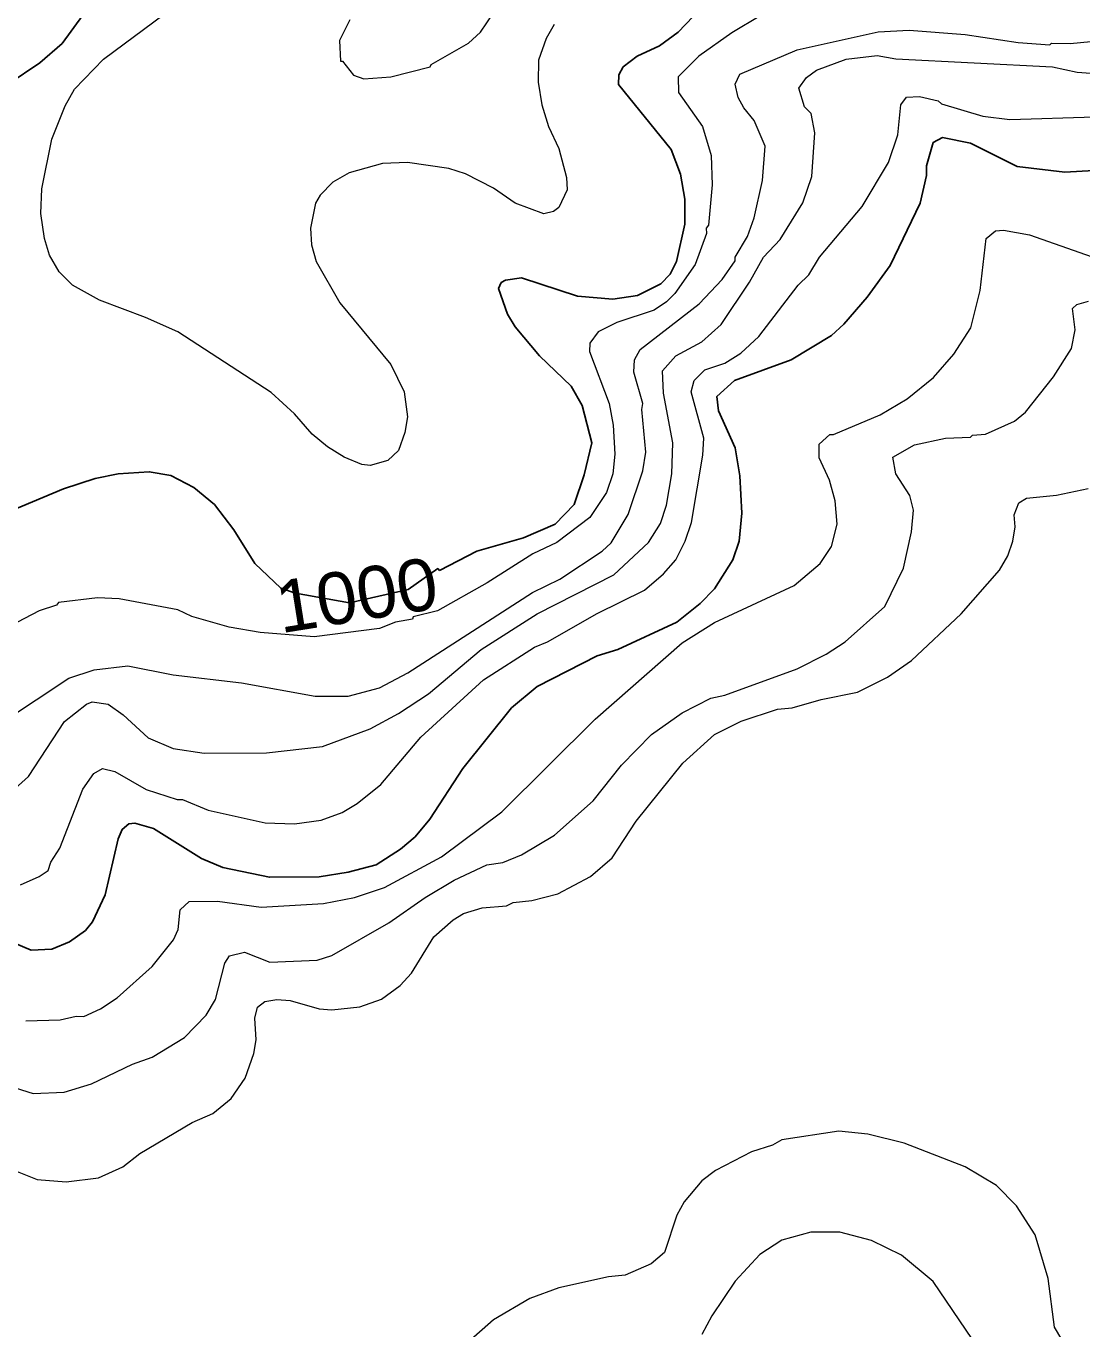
# Model space of a CAD drawing. Extents: x 265.7 to 292.1, y 7676.2 to 7704.2.
# Drawn here: x 286.697 to 288.322, y 7686.96 to 7688.966 of the extents above; entities that cross this region are included whole.
import ezdxf
from ezdxf.enums import TextEntityAlignment as Align

# ---------------------------------------------------------------- set-up
doc = ezdxf.new("R2010")
doc.units = 0
doc.header["$LTSCALE"] = 0.032
doc.layers.add('1', color=7, linetype='Continuous', lineweight=25)
doc.layers.add('2', color=7, linetype='Continuous', lineweight=13)
doc.layers.add('61', color=7, linetype='Continuous')

msp = doc.modelspace()

# ---------------------------------------------------------------- linework, layer by layer
at = {"layer": '1'}
for points in [[(286.6055, 7689.6411), (286.7013, 7689.6012), (286.7651, 7689.5605), (286.8672, 7689.4847), (286.9646, 7689.4001), (287.0276, 7689.3371), (287.1002, 7689.278), (287.1034, 7689.2541), (287.0875, 7689.2293), (287.0308, 7689.1886), (287.0061, 7689.1751), (286.9997, 7689.1751), (286.9933, 7689.1679), (286.955, 7689.1471), (286.8688, 7689.0841), (286.8297, 7689.0458), (286.7523, 7688.9389), (286.718, 7688.9094), (286.6199, 7688.8439)], [(286.659, 7688.2135), (286.7547, 7688.2534), (286.8034, 7688.2694), (286.8385, 7688.2766), (286.8864, 7688.2798), (286.9199, 7688.2742), (286.955, 7688.2558), (286.9869, 7688.2295), (287.0165, 7688.1904), (287.0492, 7688.1385), (287.0892, 7688.1006), (287.1118, 7688.093), (287.1947, 7688.0779), (287.2852, 7688.0987), (287.3304, 7688.1308), (287.3333, 7688.1281), (287.3907, 7688.1577), (287.4625, 7688.1784), (287.5112, 7688.1992), (287.5407, 7688.2295), (287.5559, 7688.275), (287.5678, 7688.3245), (287.5527, 7688.3819), (287.5359, 7688.4114), (287.4872, 7688.4585), (287.4497, 7688.5032), (287.4378, 7688.5223), (287.4242, 7688.5622), (287.4282, 7688.571), (287.4346, 7688.575), (287.4593, 7688.5782), (287.5455, 7688.5503), (287.5998, 7688.5455), (287.6381, 7688.5511), (287.674, 7688.5694), (287.6883, 7688.5838), (287.6979, 7688.6037), (287.7107, 7688.6612), (287.7107, 7688.6995), (287.7043, 7688.7378), (287.6899, 7688.7761), (287.6085, 7688.8758), (287.6093, 7688.891), (287.6157, 7688.903), (287.6373, 7688.9197), (287.6716, 7688.9357), (287.7003, 7688.9564), (287.7578, 7689.0171)], [(286.7045, 7687.5432), (286.7364, 7687.5448), (286.7635, 7687.556), (286.7882, 7687.5736), (286.7994, 7687.5871), (286.8186, 7687.6286), (286.8385, 7687.7148), (286.8449, 7687.7292), (286.8553, 7687.7379), (286.8641, 7687.7387), (286.8928, 7687.7308), (286.967, 7687.6845), (286.9997, 7687.6709), (287.0715, 7687.6557), (287.1481, 7687.6565), (287.1928, 7687.6637), (287.2359, 7687.6749), (287.2734, 7687.6988), (287.2957, 7687.718), (287.3181, 7687.7451), (287.3692, 7687.8233), (287.4442, 7687.9167), (287.4833, 7687.9494), (287.5758, 7687.9965), (287.6078, 7688.0061), (287.6987, 7688.0483), (287.7346, 7688.0771), (287.7562, 7688.0994), (287.7849, 7688.1441), (287.7945, 7688.1728), (287.7985, 7688.2159), (287.7953, 7688.2734), (287.7881, 7688.3165), (287.7626, 7688.3739), (287.7602, 7688.3955), (287.7873, 7688.4202), (287.8743, 7688.4521), (287.9365, 7688.4896), (287.9557, 7688.5072), (287.9916, 7688.5487), (288.0267, 7688.5973), (288.073, 7688.6931), (288.0825, 7688.7362), (288.0825, 7688.7506), (288.0929, 7688.7865), (288.1073, 7688.7944), (288.1504, 7688.7857), (288.2222, 7688.7498), (288.2956, 7688.741), (288.3403, 7688.7434)], [(286.5193, 7687.5313), (286.5249, 7687.56), (286.5385, 7687.5887), (286.5465, 7687.5967), (286.5624, 7687.5999), (286.5768, 7687.5975), (286.7045, 7687.5432)]]:
    msp.add_lwpolyline(points, dxfattribs=at)
at = {"layer": '2'}
for points in [[(287.1952, 7688.9756), (287.1792, 7688.9437), (287.1808, 7688.9118), (287.184, 7688.9118), (287.2008, 7688.8902), (287.2168, 7688.8846), (287.2583, 7688.8878), (287.3189, 7688.903), (287.3205, 7688.907), (287.3779, 7688.9397), (287.3963, 7688.9564), (287.4258, 7688.9995)], [(287.828, 7688.982), (287.7833, 7688.9556), (287.7322, 7688.9197), (287.7003, 7688.8878), (287.7011, 7688.8639), (287.7378, 7688.8112), (287.7514, 7688.7665), (287.753, 7688.7218), (287.7474, 7688.6596), (287.7434, 7688.6548), (287.7442, 7688.6468), (287.7266, 7688.599), (287.6955, 7688.5543), (287.6828, 7688.5415), (287.6636, 7688.5287), (287.6062, 7688.5096), (287.5774, 7688.4952), (287.5647, 7688.4777), (287.5639, 7688.4649), (287.5942, 7688.3851), (287.6006, 7688.3516), (287.603, 7688.3069), (287.5998, 7688.2766), (287.5902, 7688.2479), (287.5647, 7688.2095), (287.5136, 7688.1712), (287.4769, 7688.1537), (287.4067, 7688.109), (287.3301, 7688.0659), (287.2926, 7688.0563), (287.2918, 7688.0531), (287.2654, 7688.0484), (287.2407, 7688.0388), (287.1402, 7688.026), (287.0572, 7688.0324), (287.0093, 7688.0404), (286.9518, 7688.0571), (286.9303, 7688.0675), (286.8401, 7688.0843), (286.8066, 7688.0859), (286.7468, 7688.0787), (286.7436, 7688.0747), (286.7172, 7688.0659), (286.6614, 7688.0364)], [(287.5288, 7688.733), (287.5296, 7688.7139), (287.5168, 7688.6867), (287.5088, 7688.6803), (287.4936, 7688.6771), (287.4498, 7688.6931), (287.4162, 7688.7162), (287.3732, 7688.7386), (287.3476, 7688.7466), (287.2838, 7688.7561), (287.2455, 7688.7546), (287.1944, 7688.7402), (287.1689, 7688.7258), (287.1497, 7688.7059), (287.1425, 7688.6931), (287.1346, 7688.6548), (287.1362, 7688.6293), (287.1433, 7688.6037), (287.18, 7688.5399), (287.2582, 7688.4449), (287.279, 7688.4027), (287.2838, 7688.3644), (287.2798, 7688.3404), (287.2702, 7688.3125), (287.2535, 7688.2973), (287.2263, 7688.2893), (287.2136, 7688.2909), (287.1864, 7688.3021), (287.1609, 7688.3181), (287.137, 7688.338), (287.1098, 7688.3691), (287.0739, 7688.4019), (286.9303, 7688.4952), (286.8808, 7688.5176), (286.8098, 7688.5439), (286.7683, 7688.567), (286.7476, 7688.5878), (286.7332, 7688.6133), (286.7252, 7688.6389), (286.7196, 7688.6772), (286.7212, 7688.7155), (286.7364, 7688.7921), (286.7571, 7688.8431), (286.7715, 7688.8687), (286.8162, 7688.9149), (286.9095, 7688.9844)], [(286.8018, 7687.9749), (286.8537, 7687.9813), (286.9231, 7687.967), (287.0284, 7687.955), (287.1418, 7687.9342), (287.1928, 7687.9342), (287.2407, 7687.947), (287.2846, 7687.9702), (287.4761, 7688.0938), (287.5184, 7688.1146), (287.5838, 7688.1577), (287.5974, 7688.1704), (287.6237, 7688.2143), (287.6461, 7688.2814), (287.6508, 7688.3101), (287.6445, 7688.3755), (287.6461, 7688.3851), (287.6325, 7688.433), (287.6333, 7688.4521), (287.6421, 7688.4681), (287.733, 7688.5383), (287.7681, 7688.5758), (287.7881, 7688.6045), (287.7881, 7688.6101), (287.8072, 7688.642), (287.8176, 7688.6708), (287.8304, 7688.7282), (287.8344, 7688.7809), (287.8176, 7688.8208), (287.8017, 7688.8399), (287.7929, 7688.8559), (287.7881, 7688.8766), (287.7953, 7688.8918), (287.8839, 7688.9293), (288.0083, 7688.9572), (288.0562, 7688.9596), (288.1424, 7688.9532), (288.2238, 7688.9405), (288.2725, 7688.9373), (288.2749, 7688.9397), (288.3036, 7688.9389), (288.3674, 7688.9453)], [(287.5096, 7688.9684), (287.4976, 7688.9469)], [(287.4976, 7688.9469), (287.4857, 7688.9134), (287.4849, 7688.8798), (287.4905, 7688.8447), (287.5008, 7688.8112), (287.5168, 7688.7777), (287.5288, 7688.733)], [(286.659, 7687.7731), (286.7005, 7687.8106), (286.7563, 7687.8952), (286.7898, 7687.9223), (286.7986, 7687.9255), (286.8234, 7687.9223), (286.8465, 7687.9055), (286.8848, 7687.8704), (286.9231, 7687.8536), (286.971, 7687.8465), (287.0667, 7687.8473), (287.1529, 7687.8568), (287.2263, 7687.884), (287.2702, 7687.9079), (287.3165, 7687.9382), (287.3971, 7688.0061), (287.4833, 7688.0611), (287.6014, 7688.121), (287.6548, 7688.1712), (287.6732, 7688.2), (287.6828, 7688.2287), (287.6907, 7688.2766), (287.6923, 7688.3245), (287.678, 7688.4011), (287.6764, 7688.4354), (287.6971, 7688.4585), (287.737, 7688.48), (287.7666, 7688.5064), (287.8104, 7688.5718), (287.832, 7688.6101), (287.8575, 7688.6373), (287.8926, 7688.6939), (287.9062, 7688.7346), (287.911, 7688.8016), (287.9054, 7688.8312), (287.895, 7688.8415), (287.8862, 7688.8703), (287.8982, 7688.887), (287.9134, 7688.8982), (287.9589, 7688.9149), (288.0067, 7688.9205), (288.0355, 7688.9157), (288.2765, 7688.903), (288.3148, 7688.895), (288.3914, 7688.8894)], [(286.6885, 7687.6438), (286.7172, 7687.6566), (286.7308, 7687.6661), (286.7348, 7687.6789), (286.7491, 7687.7004), (286.7843, 7687.7914), (286.801, 7687.8154), (286.8146, 7687.8233), (286.8337, 7687.8185), (286.8816, 7687.7906), (286.9295, 7687.7754), (286.9375, 7687.7754), (286.9774, 7687.7587), (287.0651, 7687.7395), (287.1098, 7687.7379), (287.1513, 7687.7435), (287.1832, 7687.7555), (287.2064, 7687.7691), (287.2431, 7687.7986), (287.3045, 7687.8712), (287.4011, 7687.9598), (287.4793, 7688.0101), (287.4992, 7688.018), (287.5758, 7688.0619), (287.6485, 7688.0978), (287.678, 7688.1226), (287.6971, 7688.1441), (287.7115, 7688.1728), (287.7211, 7688.2016), (287.7386, 7688.3053), (287.7402, 7688.3316), (287.7203, 7688.4027), (287.725, 7688.4202), (287.7418, 7688.437), (287.7721, 7688.4473), (287.7969, 7688.4625), (287.8248, 7688.488), (287.8854, 7688.567), (287.9014, 7688.583), (287.9182, 7688.6101), (287.9836, 7688.6883), (288.0243, 7688.7562), (288.0387, 7688.7984), (288.0434, 7688.8447), (288.0522, 7688.8567), (288.0722, 7688.8575), (288.1009, 7688.8511)], [(288.1009, 7688.8511), (288.1057, 7688.8463), (288.1695, 7688.8272), (288.211, 7688.8224), (288.3419, 7688.8264), (288.4584, 7688.8407), (288.5605, 7688.8391)], [(286.6965, 7687.4347), (286.7492, 7687.4363), (286.7739, 7687.4419), (286.7859, 7687.4411), (286.8114, 7687.4531), (286.8369, 7687.4698), (286.8912, 7687.5185), (286.9239, 7687.5592), (286.9311, 7687.5752), (286.9343, 7687.6055), (286.9478, 7687.6183), (286.9917, 7687.619), (287.0588, 7687.6095), (287.1545, 7687.6151), (287.2024, 7687.6246), (287.2487, 7687.6398), (287.3365, 7687.6869), (287.429, 7687.7563), (287.5726, 7687.8991), (287.7067, 7688.0164), (287.7562, 7688.0476), (287.8791, 7688.105), (287.919, 7688.1385), (287.9365, 7688.1649), (287.9453, 7688.1992), (287.9421, 7688.2351), (287.9333, 7688.267), (287.9174, 7688.3013), (287.9174, 7688.3221), (287.9341, 7688.3372), (287.9397, 7688.3372), (288.0115, 7688.3675), (288.053, 7688.3923), (288.0937, 7688.425), (288.1248, 7688.4609), (288.1512, 7688.5016), (288.1655, 7688.5591), (288.1743, 7688.6389), (288.1887, 7688.6508), (288.2014, 7688.6516), (288.2413, 7688.6444), (288.4137, 7688.5838)], [(286.7555, 7687.3246), (286.7978, 7687.3374), (286.8609, 7687.3677), (286.8912, 7687.3789), (286.9407, 7687.4092), (286.9742, 7687.4435), (286.9885, 7687.4674), (287.0029, 7687.5233), (287.0101, 7687.5345), (287.0332, 7687.5401), (287.0723, 7687.5249), (287.1449, 7687.5281), (287.1673, 7687.5353), (287.2551, 7687.5855), (287.3109, 7687.6246), (287.3556, 7687.651), (287.4059, 7687.6749), (287.4306, 7687.6781), (287.4593, 7687.6901), (287.5104, 7687.7204), (287.5695, 7687.7731), (287.6133, 7687.8281), (287.6596, 7687.8752), (287.7067, 7687.9087), (287.7506, 7687.9311), (287.7721, 7687.9358), (287.8839, 7687.9765), (287.9285, 7687.9989), (287.9573, 7688.018), (288.0187, 7688.0723), (288.0474, 7688.1313), (288.0594, 7688.1872), (288.0626, 7688.2207), (288.057, 7688.2431), (288.0355, 7688.2766), (288.0307, 7688.3021), (288.0642, 7688.3213), (288.1121, 7688.3316), (288.1504, 7688.3332), (288.1536, 7688.3364), (288.1735, 7688.338), (288.2182, 7688.358), (288.235, 7688.3715), (288.278, 7688.4258), (288.306, 7688.4697), (288.3116, 7688.4984), (288.3076, 7688.5311), (288.3139, 7688.5375), (288.3323, 7688.5423)], [(287.6357, 7687.7419), (287.7075, 7687.8313), (287.7562, 7687.8752), (287.7977, 7687.8959), (287.8535, 7687.9143), (287.8759, 7687.9167), (287.9206, 7687.9295), (287.9764, 7687.9406), (288.0227, 7687.9638), (288.0594, 7687.9893), (288.136, 7688.0611), (288.1951, 7688.1282), (288.2078, 7688.1505), (288.2158, 7688.1728), (288.219, 7688.1952), (288.2174, 7688.2135), (288.2246, 7688.2319), (288.2366, 7688.2391), (288.2828, 7688.2439), (288.3315, 7688.2542)], [(286.4786, 7687.7946), (286.5026, 7687.8185), (286.5417, 7687.8425), (286.5943, 7687.8552), (286.6127, 7687.8632), (286.7627, 7687.9622), (286.8018, 7687.9749)], [(287.4362, 7687.6119), (287.4466, 7687.6167), (287.4753, 7687.6198), (287.5152, 7687.6302), (287.5655, 7687.6566), (287.599, 7687.6853), (287.6357, 7687.7419)], [(286.6757, 7687.2057), (286.714, 7687.1905), (286.7587, 7687.1866), (286.8082, 7687.1929), (286.8457, 7687.2097), (286.872, 7687.2304), (286.9526, 7687.2783), (286.9845, 7687.2919), (287.0125, 7687.315), (287.034, 7687.3462), (287.0476, 7687.3845), (287.0508, 7687.4052), (287.0492, 7687.4387), (287.0532, 7687.4555), (287.0643, 7687.4642), (287.0827, 7687.4674), (287.1034, 7687.4658), (287.1481, 7687.4531), (287.1673, 7687.4515), (287.2104, 7687.4563), (287.2439, 7687.4682), (287.2726, 7687.489), (287.2902, 7687.5081), (287.3245, 7687.564), (287.354, 7687.5903), (287.37, 7687.5999), (287.3987, 7687.6087), (287.4362, 7687.6119)], [(286.564, 7687.2568), (286.6023, 7687.3238), (286.6135, 7687.3382), (286.6295, 7687.3445), (286.6406, 7687.3438), (286.7077, 7687.323), (286.7555, 7687.3246)], [(288.2908, 7686.944), (288.2796, 7686.9631), (288.2701, 7687.0381), (288.2501, 7687.1052), (288.2214, 7687.1499), (288.1903, 7687.181), (288.1424, 7687.2097), (288.0482, 7687.2464), (287.9924, 7687.26), (287.9477, 7687.2648), (287.8599, 7687.2512), (287.8455, 7687.2432), (287.8136, 7687.2328), (287.7578, 7687.2041), (287.737, 7687.1881), (287.7099, 7687.1562), (287.6987, 7687.1355), (287.6796, 7687.078), (287.6588, 7687.0605), (287.6189, 7687.0429), (287.5934, 7687.0405), (287.5168, 7687.0238), (287.4721, 7687.007), (287.4162, 7686.9743), (287.3771, 7686.94)], [(288.1536, 7686.944), (288.0929, 7687.0334), (288.0442, 7687.074), (287.998, 7687.0964), (287.9493, 7687.1092), (287.9046, 7687.1092), (287.8599, 7687.0972), (287.8264, 7687.0748), (287.7881, 7687.0341), (287.7522, 7686.9807), (287.737, 7686.952)]]:
    msp.add_lwpolyline(points, dxfattribs=at)

# ---------------------------------------------------------------- texts
at = {"layer": '61', "width": 1.05}
msp.add_text('1000', height=0.08, rotation=9.059, dxfattribs=at).set_placement((287.212, 7688.0507), align=Align.CENTER)

doc.saveas('drawing.dxf')
